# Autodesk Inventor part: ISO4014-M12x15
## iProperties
Shininess: 64.0
Angle Display Precision: 2
Document Length Units: 11269
Document Angle Units: 11279
Document Time Units: 11290
Document Mass Units: 11283
Document Length Units Precision: 3
Document Angle Units Precision: 2
Created: 2001-12
Part Number: ISO4014-M12x15
Document SubType Name: Modeling
Designer: Tobben
Density: 1 g/cm^3
Density: 0.0
Volumn: 0.0
Area: 0.0
PropertySet Name: Model Information
Control State: 0
Master: False
Checked Out: False
Author: Tobben
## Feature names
1. Base1
